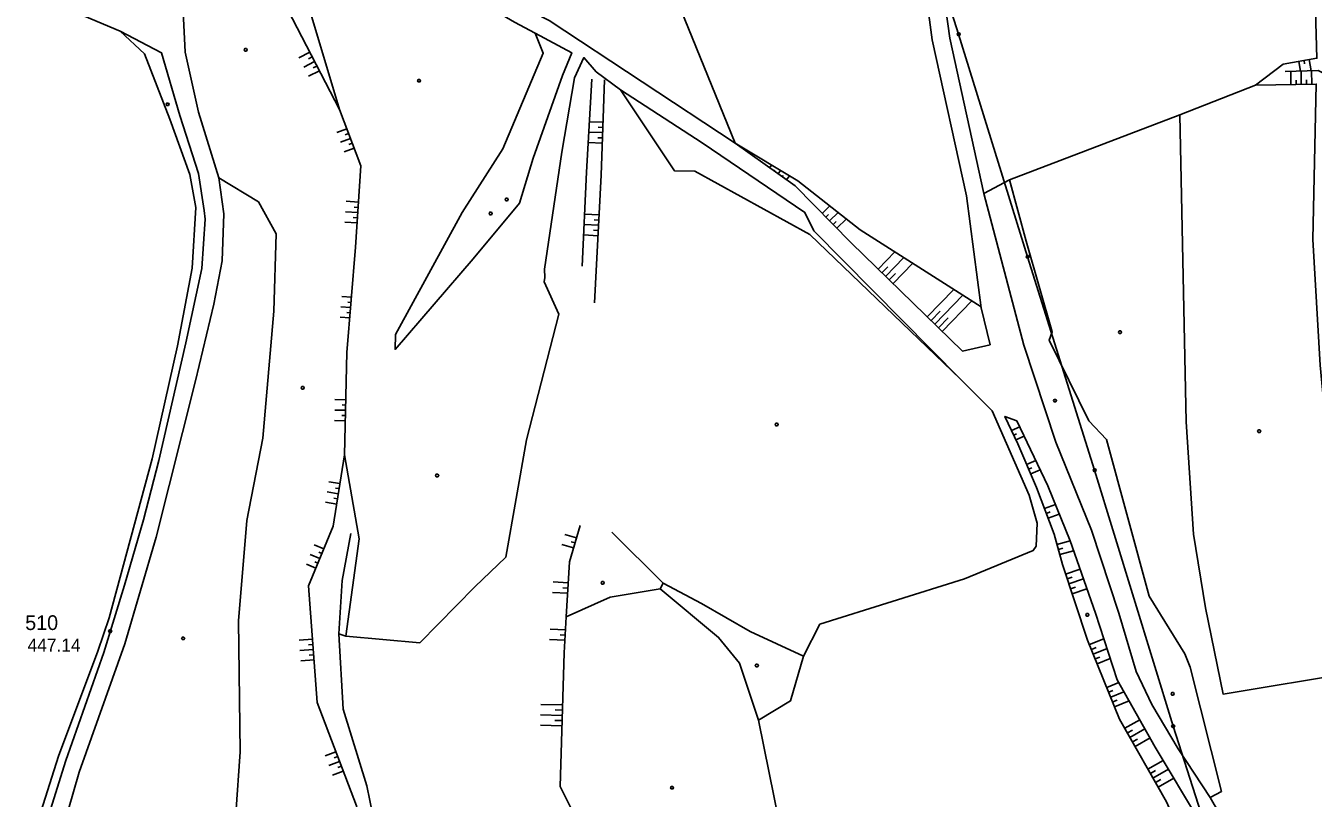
# Model space of a CAD drawing. Extents: x -664960 to -662754, y -993849 to -991145.
# Drawn here: x -664152.5 to -663855.3, y -993243.5 to -993065.3 of the extents above; entities that cross this region are included whole.
import ezdxf

# ---------------------------------------------------------------- set-up
doc = ezdxf.new("R2010")
doc.units = 0
for name, color, linetype in [('Vrstva 1', 7, 'Continuous'), ('Vrstva 13', 7, 'Continuous'), ('Vrstva 23', 7, 'Continuous'), ('Vrstva 27', 7, 'Continuous'), ('Vrstva 37', 7, 'Continuous'), ('Vrstva 57', 7, 'Continuous'), ('Vrstva 63', 7, 'Continuous'), ('Vrstva 8', 7, 'Continuous')]:
    doc.layers.add(name, color=color, linetype=linetype)

msp = doc.modelspace()

# ---------------------------------------------------------------- linework, layer by layer
at = {"layer": 'Vrstva 13'}
for points in [[(-664101.53, -993070.546), (-664101.35, -993070.846), (-664101.53, -993071.146), (-664101.89, -993071.146), (-664102.07, -993070.846), (-664101.89, -993070.546), (-664101.53, -993070.546)], [(-664061.511, -993077.68), (-664061.331, -993077.98), (-664061.511, -993078.28), (-664061.871, -993078.28), (-664062.051, -993077.98), (-664061.871, -993077.68), (-664061.511, -993077.68)], [(-664119.561, -993083.132), (-664119.381, -993083.432), (-664119.561, -993083.732), (-664119.921, -993083.732), (-664120.101, -993083.432), (-664119.921, -993083.132), (-664119.561, -993083.132)], [(-664041.303, -993105.089), (-664041.123, -993105.389), (-664041.303, -993105.689), (-664041.663, -993105.689), (-664041.843, -993105.389), (-664041.663, -993105.089), (-664041.303, -993105.089)], [(-664045.004, -993108.302), (-664044.824, -993108.602), (-664045.004, -993108.902), (-664045.364, -993108.902), (-664045.544, -993108.602), (-664045.364, -993108.302), (-664045.004, -993108.302)], [(-663899.737, -993135.694), (-663899.557, -993135.994), (-663899.737, -993136.294), (-663900.097, -993136.294), (-663900.277, -993135.994), (-663900.097, -993135.694), (-663899.737, -993135.694)], [(-664088.37, -993148.537), (-664088.19, -993148.837), (-664088.37, -993149.137), (-664088.73, -993149.137), (-664088.91, -993148.837), (-664088.73, -993148.537), (-664088.37, -993148.537)], [(-663914.738, -993151.491), (-663914.558, -993151.791), (-663914.738, -993152.091), (-663915.098, -993152.091), (-663915.278, -993151.791), (-663915.098, -993151.491), (-663914.738, -993151.491)], [(-663978.994, -993157.013), (-663978.814, -993157.313), (-663978.994, -993157.613), (-663979.354, -993157.613), (-663979.534, -993157.313), (-663979.354, -993157.013), (-663978.994, -993157.013)], [(-663867.619, -993158.556), (-663867.439, -993158.856), (-663867.619, -993159.156), (-663867.979, -993159.156), (-663868.159, -993158.856), (-663867.979, -993158.556), (-663867.619, -993158.556)], [(-664057.351, -993168.745), (-664057.171, -993169.045), (-664057.351, -993169.345), (-664057.711, -993169.345), (-664057.891, -993169.045), (-664057.711, -993168.745), (-664057.351, -993168.745)], [(-664019.135, -993193.524), (-664018.955, -993193.824), (-664019.135, -993194.124), (-664019.495, -993194.124), (-664019.675, -993193.824), (-664019.495, -993193.524), (-664019.135, -993193.524)], [(-664115.952, -993206.308), (-664115.772, -993206.608), (-664115.952, -993206.908), (-664116.312, -993206.908), (-664116.492, -993206.608), (-664116.312, -993206.308), (-664115.952, -993206.308)], [(-663983.554, -993212.585), (-663983.374, -993212.885), (-663983.554, -993213.185), (-663983.914, -993213.185), (-663984.094, -993212.885), (-663983.914, -993212.585), (-663983.554, -993212.585)], [(-663887.612, -993219.114), (-663887.432, -993219.414), (-663887.612, -993219.714), (-663887.972, -993219.714), (-663888.152, -993219.414), (-663887.972, -993219.114), (-663887.612, -993219.114)], [(-664003.126, -993240.763), (-664002.946, -993241.063), (-664003.126, -993241.363), (-664003.486, -993241.363), (-664003.666, -993241.063), (-664003.486, -993240.763), (-664003.126, -993240.763)]]:
    msp.add_lwpolyline(points, dxfattribs=at)
at = {"layer": 'Vrstva 23'}
msp.add_line((-664130.678, -993066.532), (-664121.146, -993071.534), dxfattribs=at)
for points in [[(-663929.86, -993138.95), (-663931.93, -993130.37), (-663935.36, -993104.54), (-663943.29, -993068.58), (-663949.63, -993020.84), (-663960.66, -992965.6), (-663968.44, -992924.46), (-663987.68, -992827.67), (-663995.12, -992787.99), (-663997.38, -992776.83)], [(-663990.89, -992778.63), (-663989.48, -992786.64), (-663982.61, -992825.43), (-663971.53, -992888.56), (-663963.78, -992922.8), (-663956.22, -992965.82), (-663956.23, -992966.24), (-663953.96, -992976.6), (-663945.72, -993021.27), (-663939.17, -993068.14), (-663931.37, -993104), (-663922.1, -993138.98)], [(-663815.88, -993423.57), (-663819.75, -993405.36), (-663824.31, -993392.64), (-663830.79, -993376.07), (-663837.06, -993363.48), (-663843.01, -993348.71), (-663847.89, -993337.31), (-663852.5, -993321.23), (-663857.35, -993297.27), (-663864.53, -993273.11), (-663869.95, -993259.28), (-663879.15, -993243.34), (-663886.53, -993232.14), (-663892.56, -993221.84), (-663896.18, -993214.23), (-663900.17, -993200.79), (-663906.47, -993181.7), (-663914.77, -993161.34), (-663922.1, -993138.98)], [(-663822.04, -993421.3), (-663825.37, -993406.88), (-663827.71, -993398.5), (-663836.15, -993377.65), (-663841.61, -993365.19), (-663849.31, -993346.83), (-663854.8, -993334.21), (-663858.7, -993319.26), (-663859.27, -993318.31), (-663860.4, -993312.33), (-663860.36, -993310.06), (-663861.8, -993304.26), (-663865.7, -993288.6), (-663870.3, -993274.19), (-663875.56, -993260.56), (-663881.56, -993248.78), (-663891.79, -993231.72), (-663900.57, -993216.2), (-663905.55, -993200.84), (-663911.44, -993184.13), (-663916.56, -993171.4), (-663923.7, -993156.46)]]:
    msp.add_lwpolyline(points, dxfattribs=at)
at = {"layer": 'Vrstva 27'}
for points in [[(-663988.75, -993092.41), (-664031.66, -993064.1), (-664041.89, -993058.81), (-664049.36, -993053.68), (-664056.66, -993047.27), (-664064.16, -993039.16), (-664075.63, -993026.18), (-664086.39, -993013.62), (-664100.97, -992997.24), (-664107.68, -992994.21)], [(-664115.829, -993014.333), (-664114.25, -993009.42), (-664110.98, -993004.16), (-664106.96, -993002.25), (-664103.2, -993002.9), (-664098.43, -993006.35), (-664093.97, -993011.05), (-664078.71, -993029.54), (-664068.24, -993041.69), (-664059.05, -993050.54), (-664048.87, -993059.03), (-664039.7, -993064.49), (-664034.92, -993067.05), (-664026.4, -993071.59), (-664028.58, -993076.81), (-664035.33, -993095.89)], [(-664115.645, -993071.429), (-664116.212, -993060.526), (-664114.152, -993038.9), (-664113.894, -993029.667), (-664115.56, -993017.28)], [(-664147.11, -993247.3), (-664143.19, -993234.78), (-664134.46, -993209.89), (-664129.66, -993194.38), (-664125.31, -993179.31), (-664121.78, -993165.58), (-664115.55, -993138.42), (-664111.8, -993121.28), (-664111.05, -993109.89), (-664111.3, -993107.93), (-664112.57, -993099.39), (-664116.93, -993086.04), (-664121.15, -993071.53), (-664130.68, -993066.53)], [(-664147.01, -993395.9), (-664145.28, -993381.2), (-664141.55, -993362.53), (-664135.78, -993338.59), (-664136.97, -993319.67), (-664141.74, -993304.41), (-664145.22, -993292.42), (-664146.78, -993282.88), (-664147.19, -993271.56), (-664146.28, -993262.65), (-664143.88, -993250.55), (-664140.16, -993237.45), (-664129.58, -993207.88), (-664122.4, -993183.29), (-664113.26, -993147.21), (-664109.07, -993129.57), (-664107.16, -993119.53), (-664106.79, -993108.69), (-664107.93, -993100.41), (-664112.62, -993085.27), (-664115.65, -993071.43)], [(-664028.72, -993094.44), (-664025.82, -993077.35), (-664023.66, -993072.65), (-664020.81, -993075.93), (-664015.19, -993080.08)], [(-663936.72, -993146.82), (-663970.57, -993112.62), (-663972.65, -993108.38), (-663996.35, -993092.31), (-664015.19, -993080.08)], [(-663936.72, -993146.82), (-663929.43, -993154.16), (-663920.9, -993173.61), (-663919.05, -993180.05), (-663919.27, -993185.33)], [(-663915.1, -993182.61), (-663919.18, -993171.81), (-663923.52, -993161.77), (-663926.49, -993155.43), (-663923.7, -993156.46)], [(-664051.54, -993383.38), (-664058.81, -993363.36), (-664058.78, -993356.49), (-664058.79, -993331.89), (-664060.13, -993313.2), (-664061.75, -993306.66), (-664073.02, -993280.85), (-664074.1, -993270.6), (-664074.16, -993255.88), (-664076.17, -993245.22), (-664085.19, -993221.44), (-664087.2, -993194.52), (-664081.52, -993180.73), (-664078.91, -993164.26)], [(-664048.77, -993382.43), (-664053.9, -993366.99), (-664055.33, -993357.04), (-664054.9, -993332.02), (-664056.86, -993312.19), (-664058.79, -993304.54), (-664068.83, -993279.47), (-664070.61, -993268.81), (-664070.96, -993254.16), (-664073.76, -993240.67), (-664079.2, -993222.98), (-664080.19, -993205.56), (-664079.44, -993193.25), (-664077.43, -993182.42)]]:
    msp.add_lwpolyline(points, dxfattribs=at)
at = {"layer": 'Vrstva 37'}
for points in [[(-663936.99, -993066.98), (-663936.81, -993067.28), (-663936.99, -993067.58), (-663937.35, -993067.58), (-663937.53, -993067.28), (-663937.35, -993066.98), (-663936.99, -993066.98)], [(-663921.07, -993118.28), (-663920.89, -993118.58), (-663921.07, -993118.88), (-663921.43, -993118.88), (-663921.61, -993118.58), (-663921.43, -993118.28), (-663921.07, -993118.28)], [(-663905.61, -993167.52), (-663905.43, -993167.82), (-663905.61, -993168.12), (-663905.97, -993168.12), (-663906.15, -993167.82), (-663905.97, -993167.52), (-663905.61, -993167.52)], [(-663887.48, -993226.55), (-663887.3, -993226.85), (-663887.48, -993227.15), (-663887.84, -993227.15), (-663888.02, -993226.85), (-663887.84, -993226.55), (-663887.48, -993226.55)]]:
    msp.add_lwpolyline(points, dxfattribs=at)
at = {"layer": 'Vrstva 57'}
for points in [[(-663998.5, -992779.36), (-663987.07, -992839.89), (-663975.6, -992897.65), (-663961.91, -992968.86), (-663951.475, -993022.155), (-663937.17, -993067.28)], [(-663937.17, -993067.28), (-663921.25, -993118.58), (-663905.79, -993167.82), (-663887.66, -993226.85), (-663873.48, -993270.98), (-663861.55, -993308.04), (-663843.55, -993366.56), (-663828.28, -993415.08), (-663809.04, -993475.6), (-663791.79, -993531.02), (-663772.5, -993592.28), (-663754.33, -993650.13), (-663735.8, -993708.15), (-663717.65, -993766.39)]]:
    msp.add_lwpolyline(points, dxfattribs=at)
at = {"layer": 'Vrstva 63'}
for p, q in [((-664086.922, -993071.415), (-664089.432, -993072.716)), ((-664086.37, -993072.48), (-664087.205, -993072.914)), ((-664085.817, -993073.545), (-664088.327, -993074.847)), ((-664084.712, -993075.676), (-664087.223, -993076.978)), ((-664085.265, -993074.611), (-664086.101, -993075.044)), ((-663860.474, -993078.876), (-663860.524, -993075.83)), ((-663858.635, -993073.549), (-663858.248, -993075.758)), ((-663858.075, -993078.836), (-663858.125, -993075.754)), ((-663857.453, -993073.342), (-663857.314, -993074.134)), ((-663856.271, -993073.134), (-663855.824, -993075.682)), ((-663855.675, -993078.797), (-663855.726, -993075.678)), ((-663859.274, -993078.856), (-663859.291, -993077.836)), ((-663856.875, -993078.817), (-663856.892, -993077.784)), ((-664019.23, -993087.568), (-664022.368, -993087.462)), ((-664078.387, -993089.065), (-664080.679, -993089.936)), ((-664077.96, -993090.187), (-664078.724, -993090.477)), ((-664019.31, -993089.967), (-664022.506, -993089.859)), ((-664019.27, -993088.767), (-664020.325, -993088.732)), ((-664077.534, -993091.309), (-664079.826, -993092.18)), ((-664076.681, -993093.552), (-664078.973, -993094.423)), ((-664077.108, -993092.43), (-664077.871, -993092.721)), ((-664019.391, -993092.365), (-664022.645, -993092.256)), ((-664019.351, -993091.166), (-664020.425, -993091.13)), ((-663980.799, -993098.071), (-663980.35, -993097.442)), ((-663979.821, -993098.767), (-663979.654, -993098.532)), ((-663978.844, -993099.463), (-663978.285, -993098.679)), ((-663977.866, -993100.159), (-663977.662, -993099.872)), ((-663976.889, -993100.855), (-663976.22, -993099.916)), ((-664075.842, -993108.397), (-664078.687, -993108.206)), ((-664075.681, -993106.002), (-664078.526, -993105.811)), ((-664075.761, -993107.2), (-664076.709, -993107.136)), ((-663968.654, -993108.618), (-663966.89, -993106.878)), ((-663966.97, -993110.327), (-663964.987, -993108.373)), ((-664076.003, -993110.792), (-664078.848, -993110.6)), ((-664075.922, -993109.594), (-664076.87, -993109.531)), ((-664020.264, -993111.349), (-664023.609, -993111.169)), ((-664020.135, -993108.953), (-664023.496, -993108.771)), ((-664020.2, -993110.151), (-664021.316, -993110.091)), ((-663967.812, -993109.472), (-663967.188, -993108.857)), ((-663966.127, -993111.182), (-663965.431, -993110.495)), ((-663965.285, -993112.036), (-663963.084, -993109.867)), ((-664020.394, -993113.746), (-664023.721, -993113.566)), ((-664020.329, -993112.547), (-664021.44, -993112.487)), ((-663955.75, -993121.443), (-663951.886, -993117.465)), ((-663954.029, -993123.115), (-663949.817, -993118.78)), ((-663952.308, -993124.788), (-663947.749, -993120.096)), ((-663954.89, -993122.279), (-663953.545, -993120.895)), ((-663953.168, -993123.951), (-663951.708, -993122.449)), ((-663944.396, -993132.475), (-663938.244, -993126.143)), ((-664077.309, -993127.919), (-664079.531, -993127.74)), ((-664077.405, -993129.115), (-664078.145, -993129.055)), ((-663942.674, -993134.147), (-663936.176, -993127.459)), ((-663940.953, -993135.82), (-663934.108, -993128.774)), ((-664077.502, -993130.311), (-664079.724, -993130.132)), ((-664077.598, -993131.507), (-664078.338, -993131.448)), ((-663943.535, -993133.311), (-663941.429, -993131.143)), ((-664077.694, -993132.703), (-664079.916, -993132.524)), ((-663941.814, -993134.984), (-663939.592, -993132.697)), ((-664078.604, -993151.612), (-664081.109, -993151.552)), ((-664078.633, -993152.812), (-664079.467, -993152.792)), ((-664078.662, -993154.012), (-664081.167, -993153.951)), ((-664078.691, -993155.211), (-664079.525, -993155.191)), ((-664078.72, -993156.411), (-664081.225, -993156.35)), ((-663924.963, -993158.689), (-663923.061, -993157.797)), ((-663924.454, -993159.775), (-663923.818, -993159.477)), ((-663923.945, -993160.862), (-663922.026, -993159.963)), ((-663921.48, -993166.489), (-663919.348, -993165.567)), ((-663921.004, -993167.59), (-663920.28, -993167.277)), ((-663920.528, -993168.692), (-663918.312, -993167.734)), ((-664079.961, -993170.892), (-664082.51, -993170.488)), ((-664080.337, -993173.263), (-664082.886, -993172.859)), ((-664080.149, -993172.078), (-664080.998, -993171.943)), ((-664080.712, -993175.633), (-664083.262, -993175.229)), ((-664080.525, -993174.448), (-664081.373, -993174.314)), ((-663917.345, -993176.667), (-663914.825, -993175.715)), ((-663916.921, -993177.79), (-663916.074, -993177.47)), ((-663916.497, -993178.912), (-663913.929, -993177.942)), ((-664025.363, -993183.448), (-664028.058, -993182.666)), ((-664083.674, -993185.961), (-664085.882, -993185.051)), ((-664026.032, -993185.753), (-664028.727, -993184.971)), ((-664025.698, -993184.6), (-664026.595, -993184.34)), ((-663914.466, -993184.95), (-663911.44, -993184.13)), ((-664084.589, -993188.18), (-664086.796, -993187.27)), ((-664084.131, -993187.07), (-664084.867, -993186.767)), ((-663914.152, -993186.108), (-663913.116, -993185.827)), ((-663913.838, -993187.267), (-663910.64, -993186.4)), ((-664085.503, -993190.399), (-664087.71, -993189.49)), ((-664085.046, -993189.289), (-664085.781, -993188.987)), ((-663912.481, -993191.776), (-663909.138, -993190.661)), ((-664027.259, -993193.827), (-664030.76, -993193.612)), ((-664005.34, -993193.88), (-664006.03, -993195.16)), ((-663912.101, -993192.914), (-663910.982, -993192.541)), ((-663911.722, -993194.052), (-663908.34, -993192.924)), ((-664027.406, -993196.223), (-664030.907, -993196.008)), ((-664027.333, -993195.025), (-664028.499, -993194.954)), ((-663911.342, -993195.191), (-663910.21, -993194.813)), ((-663910.962, -993196.329), (-663907.542, -993195.188)), ((-664027.911, -993204.669), (-664031.435, -993204.469)), ((-664027.979, -993205.867), (-664029.153, -993205.8)), ((-664086.283, -993206.805), (-664089.359, -993207.035)), ((-664086.104, -993209.199), (-664089.18, -993209.428)), ((-664086.193, -993208.002), (-664087.218, -993208.079)), ((-664028.047, -993207.065), (-664031.572, -993206.865)), ((-663906.983, -993208.044), (-663903.652, -993206.693)), ((-663906.531, -993209.156), (-663905.449, -993208.717)), ((-663906.08, -993210.268), (-663902.91, -993208.982)), ((-664085.925, -993211.592), (-664089.002, -993211.822)), ((-664086.015, -993210.395), (-664087.039, -993210.472)), ((-663905.629, -993211.38), (-663904.6, -993210.962)), ((-663905.178, -993212.492), (-663902.168, -993211.271)), ((-663902.966, -993217.944), (-663900.215, -993216.827)), ((-663902.515, -993219.055), (-663901.551, -993218.664)), ((-663902.064, -993220.167), (-663899.023, -993218.934)), ((-663901.613, -993221.279), (-663900.552, -993220.849)), ((-663901.162, -993222.391), (-663897.832, -993221.04)), ((-664028.65, -993224.389), (-664033.632, -993224.238)), ((-664028.577, -993221.99), (-664033.558, -993221.839)), ((-664028.614, -993223.19), (-664030.273, -993223.139)), ((-664028.723, -993226.788), (-664033.705, -993226.637)), ((-664028.687, -993225.589), (-664030.346, -993225.538)), ((-663898.8, -993227.371), (-663895.353, -993225.423)), ((-663898.209, -993228.416), (-663897.061, -993227.767)), ((-663897.619, -993229.461), (-663894.171, -993227.512)), ((-663897.028, -993230.505), (-663895.88, -993229.856)), ((-663896.437, -993231.55), (-663892.989, -993229.6)), ((-664080.897, -993232.758), (-664083.386, -993233.702)), ((-664080.046, -993235.002), (-664082.534, -993235.946)), ((-664080.471, -993233.88), (-664081.3, -993234.194)), ((-664079.62, -993236.124), (-664080.449, -993236.438)), ((-663893.493, -993236.758), (-663889.965, -993234.764)), ((-664079.195, -993237.246), (-664081.683, -993238.19)), ((-663892.903, -993237.803), (-663891.719, -993237.134)), ((-663892.312, -993238.848), (-663888.73, -993236.823)), ((-663891.722, -993239.892), (-663890.52, -993239.213)), ((-663891.131, -993240.937), (-663887.495, -993238.882))]:
    msp.add_line(p, q, dxfattribs=at)
for points in [[(-664130.678, -993066.532), (-664156.854, -993055.457), (-664171.024, -993052.13), (-664176.885, -993051.684), (-664184.1, -993048.332), (-664208.518, -993025.831), (-664225.229, -993010.614), (-664240.873, -992991.914), (-664254.272, -992978.277), (-664260.266, -992968.033), (-664273.375, -992953.363), (-664289.388, -992940.125), (-664310.911, -992926.141), (-664336.284, -992914.557), (-664354.639, -992907.946), (-664373.632, -992901.138), (-664389.166, -992898.314), (-664395.725, -992897.751), (-664408.092, -992896.554)], [(-663962.31, -992964.08), (-664000.53, -992969.44), (-664022.8, -992973.93), (-664006.71, -993048.08), (-663988.75, -993092.41)], [(-663953.96, -992976.6), (-663944.14, -992978), (-663916.87, -992989.68), (-663873.66, -993007.23), (-663861.96, -993010.62), (-663860.36, -993033.02), (-663854.94, -993056.31), (-663854.48, -993072.82), (-663862.23, -993074.18), (-663868.63, -993079.01), (-663886.15, -993085.85), (-663925.46, -993100.87), (-663931.37, -993104)], [(-664113.65, -993012.84), (-664107.7, -993013.62), (-664087.95, -993040.3), (-664086.68, -993062.58), (-664080.08, -993084.61), (-664075.12, -993097.66), (-664076.38, -993116.4), (-664078.34, -993140.71), (-664078.91, -993164.26), (-664075.53, -993183.68), (-664078.59, -993206.08)], [(-664087.95, -993040.3), (-664091.98, -993061.66), (-664080.08, -993084.61)], [(-664130.678, -993066.532), (-664125.037, -993071.808), (-664119.18, -993086.85), (-664114.57, -993099.61), (-664113.25, -993107.22), (-664114.08, -993121.25), (-664117.42, -993139.12), (-664123.32, -993165.24), (-664133.21, -993201.92), (-664135.82, -993209.56), (-664144.89, -993233.81), (-664149, -993246.64), (-664152, -993260.56), (-664154.41, -993277.57), (-664150.84, -993283.04)], [(-664035.33, -993095.89), (-664038.52, -993106.23), (-664049.2, -993119.08), (-664067.22, -993139.98), (-664067.1, -993136.55), (-664051.77, -993108.38), (-664042.36, -993093.68), (-664033.05, -993071.65), (-664034.92, -993067.05)], [(-663861.8, -993075.87), (-663854.19, -993075.63), (-663852.02, -993076.68)], [(-664021.8, -993077.64), (-664023.04, -993099.09), (-664024.06, -993120.76)], [(-664018.9, -993077.77), (-664019.64, -993099.77), (-664021.23, -993129.26)], [(-663868.63, -993079.01), (-663854.64, -993078.78), (-663855.39, -993114.64), (-663853.69, -993143.61), (-663851.46, -993167.2), (-663846.95, -993203.4), (-663845.58, -993214.39), (-663841.42, -993235.66), (-663830.04, -993262.03), (-663819.16, -993294.58), (-663811.5, -993316.83), (-663809.19, -993328.03), (-663814.43, -993335.77), (-663815.62, -993345.98), (-663811.8, -993376.39), (-663812.8, -993389.09), (-663813.91, -993393.53), (-663818.11, -993403.98), (-663819.75, -993405.36)], [(-663936.72, -993146.82), (-663971.53, -993113.48), (-663998.06, -993098.89), (-664002.77, -993098.75), (-664015.19, -993080.08)], [(-663886.15, -993085.85), (-663884.66, -993156.67), (-663882.93, -993182.57), (-663880.21, -993199.6), (-663876.12, -993219.48), (-663845.58, -993214.39)], [(-663988.75, -993092.41), (-663974.26, -993101.09), (-663959.91, -993112.36), (-663931.961, -993130.14)], [(-663929.86, -993138.95), (-663936.28, -993140.36), (-663961.97, -993115.4), (-663974.93, -993102.25), (-663988.75, -993092.41)], [(-664080.19, -993205.56), (-664078.59, -993206.08), (-664061.55, -993207.67), (-664048.85, -993194.75), (-664041.7, -993187.87), (-664036.89, -993160.8), (-664029.41, -993131.86), (-664032.79, -993124.36), (-664032.68, -993123.41), (-664032.78, -993121.44), (-664028.72, -993094.44)], [(-664147.19, -993271.56), (-664136.43, -993280.47), (-664116.6, -993285.43), (-664107.88, -993277.26), (-664103.4, -993262.64), (-664104, -993247.07), (-664103.02, -993232.82), (-664103.36, -993202.59), (-664101.44, -993179.46), (-664097.78, -993160.43), (-664095.21, -993131.12), (-664094.64, -993113.28), (-664098.78, -993105.89), (-664107.93, -993100.41)], [(-663879.15, -993243.34), (-663876.48, -993241.93), (-663883.73, -993213.24), (-663884.98, -993210.19), (-663893.16, -993196.85), (-663903.07, -993160.76), (-663907.14, -993156.47), (-663916.27, -993137.85), (-663915.61, -993135.95), (-663921.61, -993115.03), (-663925.46, -993100.87)], [(-664024.54, -993180.61), (-664026.96, -993188.95), (-664027.74, -993201.66)], [(-663919.27, -993185.33), (-663919.93, -993186.32), (-663935.84, -993192.89), (-663969.17, -993203.36), (-663972.97, -993210.73), (-663985.31, -993205.07), (-663996.5, -993198.58), (-664005.34, -993193.88), (-664017.23, -993182.09)], [(-663893.5, -993301), (-663882.23, -993305.99), (-663867.54, -993308.99), (-663867.94, -993301.99), (-663870.08, -993292.12), (-663877.58, -993270.15), (-663889.23, -993244.3), (-663900.01, -993225.23), (-663907.39, -993207.04), (-663913.2, -993189.62), (-663915.1, -993182.61)], [(-663972.97, -993210.73), (-663975.97, -993221.06), (-663983.33, -993225.46), (-663987.72, -993212.34), (-663992.55, -993206.39), (-664006.03, -993195.16), (-664017.56, -993197.12), (-664027.74, -993201.66)], [(-664027.74, -993201.66), (-664028.21, -993209.93), (-664029.15, -993240.8), (-664022.26, -993254.5), (-664014.52, -993272.37), (-664009.3, -993282.14), (-663986.99, -993294.52), (-663973.93, -993310.19), (-663967.99, -993328.89), (-663962.3, -993354.8), (-663947.76, -993384.44), (-663933.03, -993399.51), (-663933.03, -993408.97), (-663937.13, -993420.91), (-663936.54, -993450.22), (-663931.92, -993484.71), (-663931.46, -993505.55), (-663930.01, -993521.07)], [(-663907.28, -993200.91), (-663907.1, -993201.21), (-663907.28, -993201.51), (-663907.64, -993201.51), (-663907.82, -993201.21), (-663907.64, -993200.91), (-663907.28, -993200.91)], [(-663983.33, -993225.46), (-663978.52, -993249.41), (-663976.91, -993259.08)]]:
    msp.add_lwpolyline(points, dxfattribs=at)
at = {"layer": 'Vrstva 8'}
msp.add_lwpolyline([(-664132.81, -993204.67), (-664132.63, -993204.97), (-664132.81, -993205.27), (-664133.17, -993205.27), (-664133.35, -993204.97), (-664133.17, -993204.67), (-664132.81, -993204.67)], dxfattribs=at)

# ---------------------------------------------------------------- texts
at = {"layer": 'Vrstva 1'}
msp.add_text('510', height=3.4, dxfattribs=at).set_placement((-664152.594, -993204.695))
at = {"layer": 'Vrstva 63'}
msp.add_text('447.14', height=3, dxfattribs=at).set_placement((-664152.07, -993209.675))

doc.saveas('drawing.dxf')
